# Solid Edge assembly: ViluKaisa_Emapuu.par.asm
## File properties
Author: kaisa
Template: Iso Metric Assembly.asm
Last saved by: kaisa
Revision: 1
Application: Solid Edge
Username: kaisa
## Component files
ViluKaisa_Parras.par
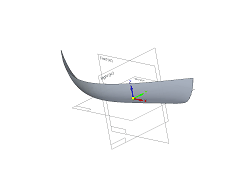
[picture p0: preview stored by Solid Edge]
